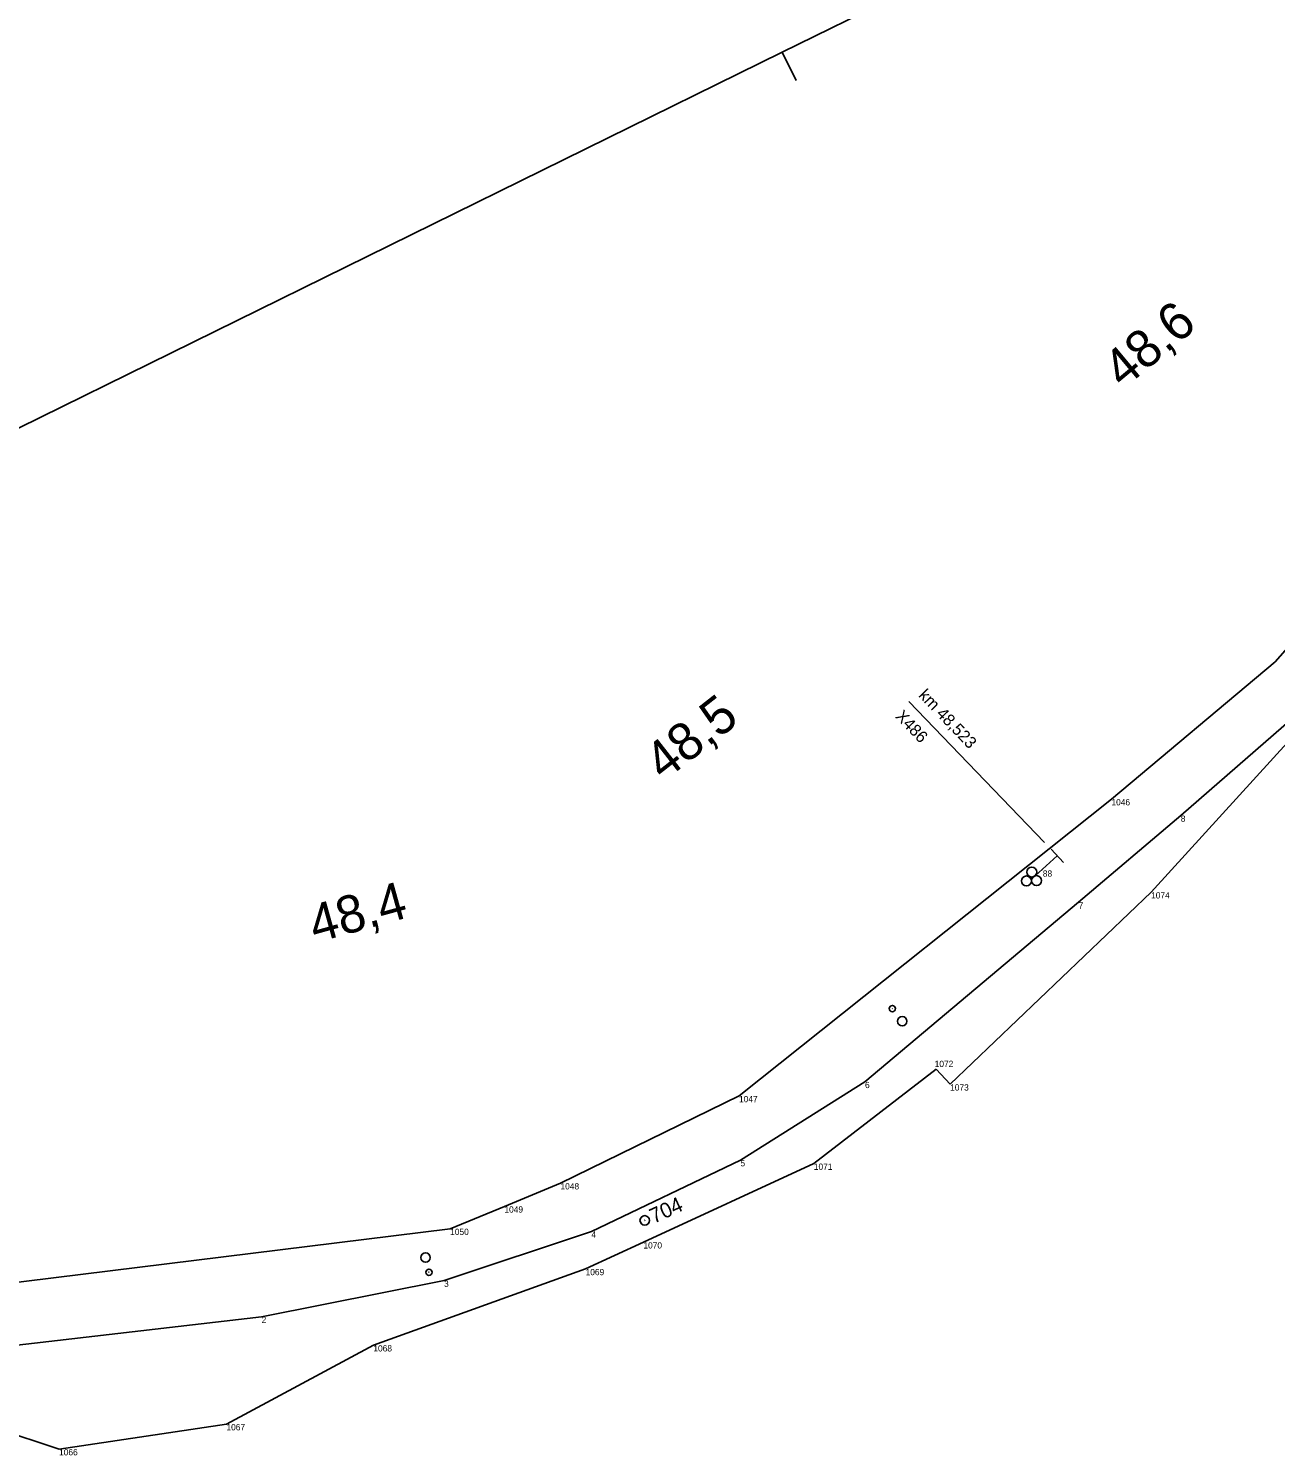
# Model space of a CAD drawing. Extents: x -679938 to -678300, y -1007495 to -1006487.
# Drawn here: x -679116.3 to -678917.3, y -1006989 to -1006761.2 of the extents above; entities that cross this region are included whole.
import ezdxf

# ---------------------------------------------------------------- set-up
doc = ezdxf.new("R2010")
doc.units = 0
for name, color, linetype in [('ramy - Sekce lichá', 7, 'Continuous'), ('SSZT nové - lomové body', 7, 'Continuous'), ('SSZT_nové', 7, 'Continuous'), ('Stávající ŽBP', 7, 'Continuous'), ('SŽDC', 7, 'Continuous'), ('SŽDC - body', 7, 'Continuous'), ('Vrstva 7', 7, 'Continuous')]:
    doc.layers.add(name, color=color, linetype=linetype)

msp = doc.modelspace()

# ---------------------------------------------------------------- linework, layer by layer
at = {"layer": 'ramy - Sekce lichá'}
for p, q in [((-678996.03, -1006764.94), (-678807.62, -1006672.19)), ((-679184.43, -1006857.69), (-678996.03, -1006764.94)), ((-678996.03, -1006764.94), (-678993.82, -1006769.43))]:
    msp.add_line(p, q, dxfattribs=at)
at = {"layer": 'SSZT nové - lomové body'}
for p, q in [((-678932.41, -1006886.82), (-678932.41, -1006886.82)), ((-678954.43, -1006895.59), (-678954.43, -1006895.59)), ((-678948.72, -1006900.67), (-678948.72, -1006900.67)), ((-678982.82, -1006929.34), (-678982.82, -1006929.34)), ((-679002.7, -1006941.83), (-679002.7, -1006941.83)), ((-679026.5, -1006953.22), (-679026.5, -1006953.22)), ((-679050.01, -1006961.07), (-679050.01, -1006961.07)), ((-679079.13, -1006966.84), (-679079.13, -1006966.84))]:
    msp.add_line(p, q, dxfattribs=at)
at = {"layer": 'SSZT_nové'}
for p, q in [((-678975.82, -1006868.59), (-678954.19, -1006891.11)), ((-678955.63, -1006896.45), (-678952.14, -1006893.25)), ((-678951.13, -1006894.33), (-678953.12, -1006892.2))]:
    msp.add_line(p, q, dxfattribs=at)
for points in [[(-678982.82, -1006929.34), (-678948.72, -1006900.67), (-678932.41, -1006886.82), (-678896.62, -1006855.69), (-678877.58, -1006840.85), (-678856.04, -1006828.01), (-678841.61, -1006821.61), (-678825.98, -1006816.5), (-678807.13, -1006811.25), (-678784.83, -1006808.82), (-678758.68, -1006808.66)], [(-679220.94, -1006983.3), (-679079.13, -1006966.84), (-679050.01, -1006961.07), (-679026.5, -1006953.22), (-679002.7, -1006941.83), (-678982.82, -1006929.34)]]:
    msp.add_lwpolyline(points, dxfattribs=at)
for centre in [(-678956.19, -1006895.84), (-678957.05, -1006897.26), (-678955.44, -1006897.21)]:
    msp.add_circle(centre, 0.792, dxfattribs=at)
at = {"layer": 'Stávající ŽBP'}
msp.add_line((-679018.02, -1006951.48), (-679017.93, -1006951.44), dxfattribs=at)
msp.add_circle((-679017.98, -1006951.46), 0.756, dxfattribs=at)
at = {"layer": 'SŽDC'}
for p, q in [((-678904.95, -1006848.11), (-678917.35, -1006862.27)), ((-678917.35, -1006862.27), (-678943.48, -1006884.2)), ((-678937.15, -1006899.06), (-678906.79, -1006865.68)), ((-678943.48, -1006884.2), (-679002.93, -1006931.59)), ((-678969.23, -1006929.73), (-678937.15, -1006899.06)), ((-678990.99, -1006942.39), (-678971.48, -1006927.29)), ((-678971.48, -1006927.29), (-678969.23, -1006929.73)), ((-679002.93, -1006931.59), (-679031.43, -1006945.52)), ((-679018.19, -1006954.95), (-678990.99, -1006942.39)), ((-679031.43, -1006945.52), (-679040.38, -1006949.22)), ((-679040.38, -1006949.22), (-679049.04, -1006952.79)), ((-679049.04, -1006952.79), (-679124.12, -1006962.07)), ((-679027.42, -1006959.21), (-679018.19, -1006954.95)), ((-679061.3, -1006971.39), (-679027.42, -1006959.21)), ((-679084.75, -1006983.99), (-679061.3, -1006971.39)), ((-679139.6, -1006978.72), (-679111.47, -1006987.98)), ((-679111.47, -1006987.98), (-679084.75, -1006983.99))]:
    msp.add_line(p, q, dxfattribs=at)
at = {"layer": 'SŽDC - body'}
for p, q in [((-678917.35, -1006862.27), (-678917.35, -1006862.27)), ((-678943.48, -1006884.2), (-678943.48, -1006884.2)), ((-678937.15, -1006899.06), (-678937.15, -1006899.06)), ((-678971.48, -1006927.29), (-678971.48, -1006927.29)), ((-679002.93, -1006931.59), (-679002.93, -1006931.59)), ((-678969.23, -1006929.73), (-678969.23, -1006929.73)), ((-678990.99, -1006942.39), (-678990.99, -1006942.39)), ((-679031.43, -1006945.52), (-679031.43, -1006945.52)), ((-679040.38, -1006949.22), (-679040.38, -1006949.22)), ((-679049.04, -1006952.79), (-679049.04, -1006952.79)), ((-679018.19, -1006954.95), (-679018.19, -1006954.95)), ((-679027.42, -1006959.21), (-679027.42, -1006959.21)), ((-679061.3, -1006971.39), (-679061.3, -1006971.39)), ((-679084.75, -1006983.99), (-679084.75, -1006983.99)), ((-679111.47, -1006987.98), (-679111.47, -1006987.98))]:
    msp.add_line(p, q, dxfattribs=at)
at = {"layer": 'Vrstva 7'}
for p, q in [((-678978.49, -1006917.67), (-678978.41, -1006917.61)), ((-679052.47, -1006959.74), (-679052.37, -1006959.74))]:
    msp.add_line(p, q, dxfattribs=at)
for centre, radius in [((-678978.45, -1006917.64), 0.5), ((-678976.87, -1006919.67), 0.75), ((-679052.96, -1006957.39), 0.75), ((-679052.42, -1006959.74), 0.5)]:
    msp.add_circle(centre, radius, dxfattribs=at)

# ---------------------------------------------------------------- texts
at = {"layer": 'SSZT nové - lomové body'}
for s, p in [('8', (-678932.41, -1006887.82)), ('88', (-678954.43, -1006896.59)), ('7', (-678948.72, -1006901.67)), ('6', (-678982.82, -1006930.34)), ('5', (-679002.7, -1006942.83)), ('4', (-679026.5, -1006954.22)), ('3', (-679050.01, -1006962.07)), ('2', (-679079.13, -1006967.84))]:
    msp.add_text(s, height=1, dxfattribs=at).set_placement(p)
at = {"layer": 'SSZT_nové'}
for s, p in [('km 48,523', (-678974.38, -1006867.72)), ('X486', (-678978.08, -1006871.09))]:
    msp.add_text(s, height=1.9, rotation=313.7441, dxfattribs=at).set_placement(p)
at = {"layer": 'Stávající ŽBP'}
msp.add_text('704', height=2.4, rotation=24.3976, dxfattribs=at).set_placement((-679016.53, -1006952.01))
at = {"layer": 'SŽDC - body'}
for s, p in [('1046', (-678943.48, -1006885.2)), ('1074', (-678937.15, -1006900.06)), ('1072', (-678971.7, -1006926.97)), ('1073', (-678969.23, -1006930.73)), ('1047', (-679002.93, -1006932.59)), ('1071', (-678990.99, -1006943.39)), ('1048', (-679031.43, -1006946.52)), ('1049', (-679040.38, -1006950.22)), ('1050', (-679049.04, -1006953.79)), ('1070', (-679018.19, -1006955.95)), ('1069', (-679027.42, -1006960.21)), ('1068', (-679061.3, -1006972.39)), ('1067', (-679084.75, -1006984.99)), ('1066', (-679111.47, -1006988.98))]:
    msp.add_text(s, height=1, dxfattribs=at).set_placement(p)
at = {"layer": 'Vrstva 7'}
for s, rotation, p in [('48,6', 39.8621, (-678941.6, -1006818.82)), ('48,5', 38.0408, (-679014.95, -1006881.44)), ('48,4', 15.4897, (-679070.59, -1006907.2))]:
    msp.add_text(s, height=6, rotation=rotation, dxfattribs=at).set_placement(p)

doc.saveas('drawing.dxf')
